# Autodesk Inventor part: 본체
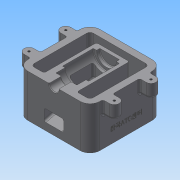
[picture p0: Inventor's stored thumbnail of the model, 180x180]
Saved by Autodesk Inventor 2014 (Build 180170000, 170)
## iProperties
Created: 2018-01
Part Number: 본체
Material: 일반
Document SubType Name: Modeling
Designer: 601-24
Density: 1 g/cm^3
Appearance: 기본값
Author: 601-24
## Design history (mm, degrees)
sketch "스케치1"
  geometry: L1 (-55, -55)-(55, -55); L2 (55, -55)-(55, 55); L3 (55, 55)-(-55, 55); L4 (-55, 55)-(-55, -55); L5 (-55, -55)-(55, 55); L6 (55, -55)-(-55, 55); 1 further point
  constraints: 12 end point, 2 midpoint, 2 parallel, 1 horizontal, 1 perpendicular
  dimensions: "d0" = 110 distance between parallel lines of L1 L3; "d1" = 110 distance between parallel lines of L4 L2
extrude "돌출1" new body sketch "스케치1" stored distance "d2" = 65; taper "d3" = 0 deg
sketch "스케치2"
  geometry: L1 (-55, -55)-(55, -55) reference; L2 (55, -55)-(55, 55) reference; L3 (55, 55)-(-55, 55) reference; L4 (-55, 55)-(-55, -55) reference; L5 (-55, -55)-(55, -55) reference; L6 (55, -55)-(55, 55) reference; L7 (55, 55)-(-55, 55) reference; L8 (-55, 55)-(-55, -55) reference; L9 (-45, 45)-(45, 45); L10 (45, 45)-(45, -45); L11 (45, -45)-(-45, -45); L12 (-45, -45)-(-45, 45); L13 (-25, 35)-(25, 35); L14 (25, 35)-(25, -45); L15 (25, -45)-(-25, -45); L16 (-25, -45)-(-25, 35); 1 further point
  constraints: 16 end point, 4 parallel, 2 horizontal, 2 perpendicular
  dimensions: "d4" = 10 distance between parallel lines of L9 L3; "d5" = 10 distance between parallel lines of L4 L12; "d6" = 10 distance between parallel lines of L1 L11; "d7" = 10 distance between parallel lines of L2 L10; "d8" = 50 distance between parallel lines of L14 L16; "d9" = 30 distance between parallel lines of L4 L16; "d10" = 20 distance between parallel lines of L3 L13; "d11" = 10 distance between parallel lines of L1 L15
extrude "돌출2" cut sketch "스케치2" stored distance "d12" = 65; taper "d13" = 0 deg
sketch "스케치3"
  geometry: L1 (-45, -32.5)-(35, -32.5) reference; L2 (-45, -32.5)-(-45, 32.5) reference; L3 (35, 32.5)-(-45, 32.5) reference; L4 (35, 32.5)-(35, -32.5) reference; L5 (-55, -32.5)-(55, -32.5) reference; L6 (55, 32.5)-(-55, 32.5) reference; L7 (-45, -23.936)-(35, -2.5); 1 further point
  constraints: 2 end point, 2 point on line
  dimensions: "d14" = 30 distance from line of L5 L7.end; "d15" = 105 deg angle of L2 L7
extrude "돌출3" cut sketch "스케치3" stored distance "d16" = 65; taper "d17" = 0 deg
sketch "스케치4"
  geometry: L1 (0, 0)-(110, 0) reference; L2 (110, -65)-(0, -65) reference; L3 (0, -65)-(0, 0) reference; L4 (0, 0)-(110, 0) reference; L5 (110, 0)-(110, -65) reference; C1 r 7.5 at (55, 0); 1 further point
  constraints: 1 centre point, 1 horizontal alignment, 1 vertical alignment
  dimensions: "d18" = 15 diameter of C1
extrude "돌출4" cut sketch "스케치4" distance "d19" = 19; taper "d20" = 0 deg
sketch "스케치5"
  geometry: C1 r 16 at (55, 0); A1 r 7.5 centre (55, 0) between (47.5, 0) and (62.5, 0) reference; 1 further point
  constraints: 1 centre point, 1 coincident
  dimensions: "d21" = 32 diameter of C1
extrude "돌출5" cut sketch "스케치5" distance "d22" = 14; taper "d23" = 0 deg
sketch "스케치6"
  geometry: C1 r 20 at (55, 0); A1 r 16 centre (55, 0) between (39, 0) and (71, 0) reference; 1 further point
  constraints: 1 centre point, 1 coincident
  dimensions: "d24" = 40 diameter of C1
extrude "돌출6" cut sketch "스케치6" distance "d25" = 47; taper "d26" = 0 deg
sketch "스케치7"
  geometry: C1 r 15 at (55, 0); A1 r 20 centre (55, 0) between (35, 0) and (75, 0) reference; 1 further point
  constraints: 1 centre point, 1 coincident
  dimensions: "d27" = 30 diameter of C1
extrude "돌출7" cut sketch "스케치7" distance "d28" = 5; taper "d29" = 0 deg
sketch "스케치8"
  geometry: L1 (35, -2.5)-(-45, -23.936) reference; L2 (-55, 32.5)-(-55, -32.5) reference; L3 (20, -1.343)-(-55, -21.439); L4 (-17, 22.5)-(20, 22.5); L5 (-22, 16.5)-(-22, 32.5) reference; L6 (25, 17.5)-(25, 32.5) reference; L7 (-22, 12.5)-(25, 12.5) reference; L8 (-17, 22.5)-(-17, 6.743); L9 (20, 22.5)-(20, -1.343); L10 (-17, 6.743)-(-55, -3.439); 3 further points
  constraints: 10 end point, 3 parallel, 2 midpoint, 2 perpendicular, 2 point on line, 1 vertical alignment
  dimensions: "d30" = 5 distance between parallel lines of L1 L3; "d31" = 18 distance of L3.end L10.end; "d32" = 37 distance of L4.start L4.end; "d33" = 10 distance from line of point (1.5, 12.5) L4
extrude "돌출8" cut sketch "스케치8" stored distance "d34" = 30; taper "d35" = 0 deg
fillet "모깎기1" dims "d36" = 1
chamfer "모따기1" distance "d37" = 1; stored, may be unused: second distance "d38" = 2, angle "d39" = 45 deg
fillet "모깎기2" dims "d40" = 15
fillet "모깎기3" dims "d41" = 5
fillet "모깎기5" dims "d43" = 3
fillet "모깎기6" dims "d44" = 3
fillet "모깎기7" dims "d45" = 3
fillet "모깎기8" dims "d46" = 3
fillet "모깎기9" dims "d47" = 3
fillet "모깎기10" dims "d48" = 3
sketch "스케치9"
  geometry: L1 (-55, 40)-(-55, -40) reference; L2 (-40, -55)-(-8.5, -55) reference; L3 (-65, 35.5)-(-55, 35.5); L4 (-65, 20.5)-(-55, 20.5); L5 (-65, -20.5)-(-55, -20.5); L6 (-65, -35.5)-(-55, -35.5); A1 r 7.5 centre (-65, -28) between (-65, -20.5) and (-65, -35.5); A2 r 7.5 centre (-65, 28) between (-65, 35.5) and (-65, 20.5); 1 further point
  constraints: 8 end point, 4 perpendicular, 4 point on circle, 4 point on line, 4 tangent, 2 centre point
  dimensions: "d49" = 15 diameter of A1; "d50" = 15 diameter of A2; "d51" = 10 distance from line of A2.centre L1; "d52" = 10 distance from line of A1.centre L1; "d53" = 27 distance from line of A1.centre L2; "d54" = 56 distance of A1.centre A2.centre
extrude "돌출9" join sketch "스케치9" distance "d55" = 20; taper "d56" = 0 deg
fillet "모깎기11" dims "d57" = 3
fillet "모깎기12" dims "d58" = 3
fillet "모깎기13" dims "d59" = 3
fillet "모깎기14" dims "d60" = 3
sketch "스케치10"
  geometry: A1 r 7.5 centre (-65, 28) between (-65, 35.5) and (-65, 20.5) reference; A2 r 7.5 centre (-65, -28) between (-65, -20.5) and (-65, -35.5) reference; A3 r 7.5 centre (65, -28) between (65, -35.5) and (65, -20.5) reference; A4 r 7.5 centre (65, 28) between (65, 20.5) and (65, 35.5) reference; 5 further points
  constraints: 4 coincident
hole "구멍1" sketch "스케치10" at (-65, 28), (65, -28), (65, 28), (-65, -28) diameter "d61" = 3.242; stored, may be unused: countersink angle "d65" = 90 deg, drill point angle "d67" = 118 deg; dims "d62" = 9, "d63" = 4, "d64" = 2, "d66" = 11
sketch "스케치11"
  geometry: L1 (0, 80)-(0, 0) reference; L2 (-65, -15)-(0, -15) reference; 2 further points
  constraints: 1 other
  dimensions: "d68" = 55 distance from line of point (-20, 40) L2; "d69" = 20 distance from line of point (-20, 40) L1
feature "엠보싱1" sketch "스케치11" dims "d0" = 110, "d1" = 110, "d4" = 10, "d70" = 0.5, "d71" = 0
node "솔리드1"
mirror "대칭1"
node "투영된 루프1"
node "투영된 루프2"
node "절단 모서리 투영1"
